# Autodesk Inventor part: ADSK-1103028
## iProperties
Shininess: 41.0
Length Units: 11272
Angle Units: 11279
Time Units: 11290
Mass Units: 11286
Length Display Precision: 4
Angle Display Precision: 2
Compacted: True
Created: 2000-06
Part Number: ADSK-1103028
Document SubType Name: Modeling
Description: 24 TOOTH CLUTCH GEAR
Mass: 6.16542 g
Surface Area: 11.6587 cm^2
Volume: 0.786406 cm^3
Density: 7.84 g/cm^3
Material: Steel, High Strength Low Alloy
Density: 0.0
Volumn: 0.0
Area: 0.0
PropertySet Name: Model Information
Control State: 0
Master: False
Checked Out: False
Author: Autodesk, Inc.
